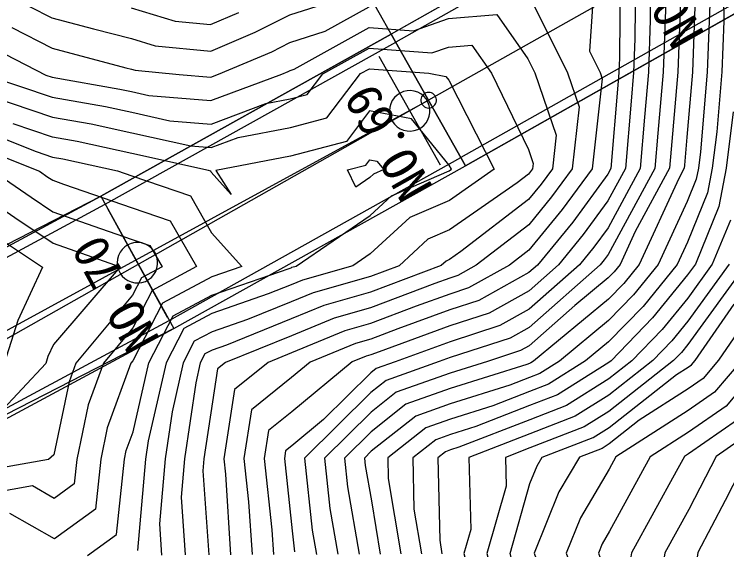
# Model space of a CAD drawing. Extents: x 42655 to 43811, y -141820 to -141156.
# Drawn here: x 42750.61 to 42796.32, y -141642.88 to -141608.54 of the extents above; entities that cross this region are included whole.
import ezdxf

# ---------------------------------------------------------------- set-up
doc = ezdxf.new("R2010")
doc.units = 0
for name, color, linetype in [('D-BMK-HTXT_1', 7, 'Continuous'), ('D-BMK_1', 7, 'Continuous'), ('D-STR-STR2トンネル', 7, 'Continuous'), ('ZE_HICN', 7, 'Continuous'), ('ZE_LWCN', 7, 'Continuous'), ('着色', 7, 'Continuous')]:
    doc.layers.add(name, color=color, linetype=linetype)

msp = doc.modelspace()

# ---------------------------------------------------------------- linework, layer by layer
at = {"layer": 'D-BMK-HTXT_1'}
for p, q in [((42777.191, -141614.053), (42738.344, -141545.264)), ((42777.945, -141618.22), (42774.016, -141611.252)), ((42777.191, -141614.053), (42724.628, -141643.736)), ((42760.439, -141627.975), (42756.58, -141620.967))]:
    msp.add_line(p, q, dxfattribs=at)
for points in [[(42774.68, -141614.736), (42774.701, -141614.968), (42774.763, -141615.193), (42774.864, -141615.403), (42775.001, -141615.591), (42775.17, -141615.752), (42775.364, -141615.881), (42775.579, -141615.972), (42775.806, -141616.024), (42776.039, -141616.035), (42776.27, -141616.003), (42776.491, -141615.931), (42776.696, -141615.821), (42776.879, -141615.676), (42777.032, -141615.5), (42777.152, -141615.3), (42777.233, -141615.082), (42777.275, -141614.853), (42777.275, -141614.619), (42777.233, -141614.39), (42777.152, -141614.172), (42777.032, -141613.972), (42776.879, -141613.796), (42776.696, -141613.651), (42776.491, -141613.541), (42776.27, -141613.469), (42776.039, -141613.437), (42775.806, -141613.448), (42775.579, -141613.5), (42775.364, -141613.591), (42775.17, -141613.72), (42775.001, -141613.881), (42774.864, -141614.069), (42774.763, -141614.279), (42774.701, -141614.504), (42774.68, -141614.736)], [(42757.21, -141624.471), (42757.231, -141624.703), (42757.293, -141624.928), (42757.394, -141625.138), (42757.531, -141625.327), (42757.699, -141625.488), (42757.894, -141625.616), (42758.108, -141625.708), (42758.335, -141625.759), (42758.568, -141625.77), (42758.799, -141625.739), (42759.021, -141625.667), (42759.226, -141625.556), (42759.408, -141625.411), (42759.561, -141625.235), (42759.681, -141625.035), (42759.763, -141624.817), (42759.804, -141624.588), (42759.804, -141624.355), (42759.763, -141624.125), (42759.681, -141623.907), (42759.561, -141623.707), (42759.408, -141623.532), (42759.226, -141623.386), (42759.021, -141623.276), (42758.799, -141623.204), (42758.568, -141623.173), (42758.335, -141623.183), (42758.108, -141623.235), (42757.894, -141623.326), (42757.699, -141623.455), (42757.531, -141623.616), (42757.394, -141623.804), (42757.293, -141624.014), (42757.231, -141624.239), (42757.21, -141624.471)]]:
    msp.add_lwpolyline(points, dxfattribs=at)
at = {"layer": 'D-BMK_1'}
msp.add_line((42932.715, -141526.226), (42777.191, -141614.053), dxfattribs=at)
for points in [[(42777.191, -141613.553), (42777.099, -141613.561), (42777.01, -141613.587), (42776.928, -141613.628), (42776.854, -141613.683), (42776.792, -141613.752), (42776.743, -141613.83), (42776.71, -141613.916), (42776.693, -141614.007), (42776.693, -141614.099), (42776.71, -141614.19), (42776.743, -141614.276), (42776.792, -141614.354), (42776.854, -141614.422), (42776.928, -141614.478), (42777.01, -141614.519), (42777.099, -141614.544), (42777.191, -141614.553)], [(42777.191, -141614.553), (42777.283, -141614.544), (42777.371, -141614.519), (42777.454, -141614.478), (42777.528, -141614.422), (42777.59, -141614.354), (42777.638, -141614.276), (42777.672, -141614.19), (42777.689, -141614.099), (42777.689, -141614.007), (42777.672, -141613.916), (42777.638, -141613.83), (42777.59, -141613.752), (42777.528, -141613.683), (42777.454, -141613.628), (42777.371, -141613.587), (42777.283, -141613.561), (42777.191, -141613.553)], [(42724.628, -141642.707), (42777.191, -141614.053)]]:
    msp.add_lwpolyline(points, dxfattribs=at)
at = {"layer": 'D-STR-STR2トンネル'}
for p, q in [((43087.053, -141433.469), (42774.793, -141609.807)), ((43087.348, -141433.992), (42775.088, -141610.33)), ((43091.527, -141441.393), (42779.268, -141617.731)), ((43091.822, -141441.915), (42779.563, -141618.253))]:
    msp.add_line(p, q, dxfattribs=at)
for points in [[(42756.158, -141620.2), (42774.793, -141609.807)], [(42756.447, -141620.726), (42775.088, -141610.33)], [(42760.547, -141628.171), (42779.268, -141617.731)], [(42760.837, -141628.697), (42779.563, -141618.253)], [(42724.628, -141637.196), (42756.158, -141620.2)], [(42724.628, -141637.875), (42756.447, -141620.726)], [(42724.628, -141647.478), (42760.547, -141628.171)], [(42724.628, -141648.156), (42760.837, -141628.697)]]:
    msp.add_lwpolyline(points, dxfattribs=at)
at = {"layer": 'ZE_HICN'}
for points in [[(42783.548, -141607.155), (42786.106, -141612.286), (42786.855, -141614.481), (42786.406, -141618.447), (42785.086, -141620.242), (42783.617, -141622.038), (42780.244, -141624.639), (42779.077, -141625.289), (42778.545, -141625.461), (42777.589, -141625.811), (42773.466, -141627.37), (42771.14, -141628.024), (42768.386, -141629.163), (42764.153, -141630.876), (42763.644, -141631.287), (42763.317, -141633.394), (42762.773, -141637.045), (42762.707, -141637.81), (42763.09, -141643.207)], [(42792.403, -141607.698), (42792.235, -141612.257), (42791.9, -141616.161), (42791.713, -141618.423), (42788.714, -141623.947), (42788.461, -141624.291), (42788.207, -141624.602), (42783.648, -141628.626), (42782.426, -141629.307), (42778.569, -141630.554), (42777.863, -141630.812), (42774.467, -141632.015), (42773.491, -141632.786), (42769.23, -141637.015), (42769.721, -141641.628), (42769.991, -141643.174)], [(42750.462, -141609.398), (42753.035, -141610.715), (42757.758, -141611.969), (42758.129, -141612.062), (42758.363, -141612.133), (42761.184, -141612.402), (42763.22, -141612.573), (42763.708, -141612.39), (42767.123, -141610.947), (42768.298, -141610.356), (42770.549, -141609.628), (42773.376, -141608.061)], [(42796.733, -141614.799), (42796.277, -141618.401), (42795.822, -141620.867), (42794.306, -141624.573), (42793.809, -141625.259), (42791.562, -141628.012), (42788.894, -141630.761), (42788.747, -141630.876), (42785.463, -141632.95), (42783.671, -141633.637), (42780.227, -141634.98), (42778.592, -141635.493), (42777.645, -141635.828), (42776.183, -141636.983), (42776.25, -141640.283), (42776.729, -141643.143)], [(42747.97, -141615.729), (42752.022, -141617.343), (42753.067, -141617.695), (42753.721, -141617.808), (42757.224, -141618.583), (42758.161, -141618.905), (42761.908, -141620.193), (42763.267, -141622.547), (42765.215, -141624.709), (42763.28, -141625.375), (42760.127, -141627.067), (42758.216, -141630.757), (42758.093, -141630.904), (42756.569, -141635.054), (42756.152, -141637.076), (42755.811, -141640.273), (42753.181, -141642.187), (42750.332, -141640.545)], [(42772.513, -141619.622), (42771.991, -141618.514), (42773.173, -141618.206), (42773.421, -141617.879), (42773.868, -141617.965), (42774.309, -141618.504), (42773.657, -141618.787), (42773.427, -141618.999), (42772.513, -141619.622)], [(42798.902, -141626.221), (42795.789, -141630.729), (42794.8, -141631.897), (42793.843, -141632.56), (42790.693, -141634.579), (42788.771, -141636.09), (42788.318, -141636.376), (42786.864, -141636.933), (42785.536, -141639.167), (42783.963, -141643.109), (42785.426, -141647.217), (42785.521, -141649.265), (42786.771, -141651.77), (42788.291, -141655.415), (42786.654, -141658.892), (42785.999, -141661.588), (42786.78, -141664.154), (42788.915, -141666.931), (42789.563, -141667.734), (42791.86, -141670.338), (42794.029, -141672.519)], [(42797.674, -141636.883), (42796.215, -141639.722), (42794.464, -141643.06), (42793.909, -141646.814), (42793.595, -141648.835), (42793.615, -141649.227), (42793.926, -141650.324), (42795.097, -141655.383), (42793.966, -141658.916), (42792.98, -141661.555), (42793.984, -141662.795), (42797.426, -141665.688)]]:
    msp.add_lwpolyline(points, dxfattribs=at)
at = {"layer": 'ZE_LWCN'}
for points in [[(42787.84, -141606.115), (42787.511, -141610.896), (42788.199, -141612.276), (42788.335, -141612.672), (42787.681, -141618.441), (42785.761, -141621.052), (42783.625, -141623.664), (42782.373, -141624.629), (42779.747, -141626.093), (42778.55, -141626.48), (42776.398, -141627.267), (42773.47, -141628.374), (42771.819, -141628.838), (42768.391, -141630.256), (42766.889, -141630.864), (42764.738, -141632.599), (42764.048, -141637.039), (42764.155, -141638.027), (42764.49, -141643.2)], [(42789.475, -141606.108), (42789.432, -141611.33), (42789.398, -141612.271), (42789.329, -141613.076), (42788.887, -141618.436), (42788.691, -141618.797), (42786.436, -141621.862), (42784.18, -141624.62), (42783.632, -141625.104), (42780.416, -141626.896), (42778.554, -141627.499), (42775.208, -141628.722), (42773.475, -141629.377), (42772.498, -141629.652), (42769.599, -141630.851), (42768.398, -141631.84), (42765.831, -141633.91), (42765.346, -141637.033), (42765.646, -141639.817), (42765.866, -141643.194)], [(42790.455, -141606.103), (42790.423, -141610.119), (42790.344, -141612.266), (42790.186, -141614.104), (42789.829, -141618.431), (42788.699, -141620.514), (42787.111, -141622.672), (42785.522, -141624.614), (42783.637, -141626.278), (42781.086, -141627.7), (42778.559, -141628.517), (42774.017, -141630.178), (42773.48, -141630.381), (42773.176, -141630.466), (42772.277, -141630.838), (42768.408, -141634.025), (42766.924, -141635.222), (42766.644, -141637.027), (42767.138, -141641.607), (42767.241, -141643.187)], [(42791.435, -141606.099), (42791.413, -141608.909), (42791.289, -141612.262), (42791.043, -141615.133), (42790.771, -141618.427), (42788.706, -141622.23), (42787.786, -141623.482), (42786.865, -141624.608), (42783.643, -141627.452), (42781.756, -141628.503), (42778.564, -141629.536), (42775.036, -141630.826), (42773.831, -141631.252), (42773.485, -141631.526), (42770.457, -141634.531), (42768.418, -141636.21), (42768.018, -141636.534), (42767.942, -141637.021), (42768.444, -141641.672), (42768.587, -141643.015)], [(42796.082, -141606.077), (42796.129, -141608.979), (42796.01, -141612.24), (42795.681, -141616.085), (42795.387, -141618.405), (42795.094, -141619.993), (42793.799, -141623.159), (42793.145, -141624.579), (42790.947, -141627.273), (42788.741, -141629.546), (42787.261, -141630.769), (42784.892, -141632.265), (42783.667, -141632.734), (42781.313, -141633.653), (42778.587, -141634.507), (42777.009, -141635.065), (42774.573, -141636.99), (42774.6, -141638.302), (42775.411, -141643.149)], [(42793.393, -141606.487), (42793.181, -141612.253), (42792.757, -141617.189), (42792.656, -141618.418), (42790.451, -141622.48), (42789.476, -141624.596), (42789.099, -141625.057), (42788.721, -141625.446), (42786.569, -141627.226), (42783.653, -141629.799), (42783.095, -141630.11), (42780.97, -141630.798), (42778.573, -141631.549), (42775.103, -141632.777), (42773.497, -141634.046), (42770.511, -141637.009), (42770.856, -141640.241), (42771.366, -141643.168)], [(42794.324, -141606.813), (42794.125, -141612.249), (42793.768, -141616.428), (42793.614, -141618.218), (42793.598, -141618.414), (42793.246, -141619.062), (42790.699, -141624.59), (42789.715, -141625.796), (42788.728, -141626.813), (42783.925, -141630.784), (42783.749, -141630.895), (42783.659, -141630.93), (42783.484, -141630.998), (42778.578, -141632.535), (42775.738, -141633.54), (42773.503, -141635.307), (42771.793, -141637.003), (42771.99, -141638.854), (42772.741, -141643.162)], [(42751.577, -141608.035), (42753.026, -141608.777), (42755.687, -141609.484), (42758.12, -141610.093), (42759.65, -141610.559), (42763.212, -141610.899), (42766.074, -141609.689), (42768.29, -141608.575), (42772.534, -141607.202)], [(42758.111, -141608.124), (42760.938, -141608.985), (42763.204, -141609.201), (42765.026, -141608.431)], [(42795.227, -141607.896), (42795.067, -141612.244), (42794.629, -141617.371), (42794.498, -141618.41), (42794.367, -141619.12), (42793.787, -141620.537), (42791.922, -141624.584), (42790.331, -141626.535), (42788.734, -141628.179), (42785.593, -141630.776), (42784.321, -141631.58), (42783.663, -141631.832), (42782.399, -141632.325), (42778.582, -141633.521), (42776.374, -141634.303), (42773.508, -141636.567), (42773.075, -141636.997), (42773.125, -141637.467), (42773.523, -141639.752), (42774.093, -141643.155)], [(42749.348, -141610.76), (42752.631, -141612.442), (42753.044, -141612.581), (42757.381, -141613.334), (42758.136, -141613.501), (42759.238, -141613.744), (42763.227, -141614.08), (42767.778, -141612.371), (42768.171, -141612.205), (42768.306, -141612.137), (42768.565, -141612.054), (42773.382, -141609.383), (42776.22, -141609.606), (42778.467, -141608.821), (42781.558, -141608.563), (42783.568, -141611.405), (42784.012, -141612.296), (42785.376, -141616.29), (42785.131, -141618.453), (42784.411, -141619.432), (42783.61, -141620.412), (42779.264, -141623.763), (42778.539, -141624.267), (42778.309, -141624.368), (42778.003, -141624.649), (42773.461, -141626.366), (42770.462, -141627.21), (42768.381, -141628.07), (42764.229, -141629.751), (42763.302, -141630.07), (42762.838, -141630.319), (42762.545, -141630.884), (42762.254, -141632.166), (42761.526, -141637.051), (42761.313, -141639.514), (42761.576, -141643.214)], [(42748.89, -141612.459), (42753.05, -141613.859), (42756.466, -141614.452), (42758.142, -141614.823), (42760.588, -141615.364), (42763.234, -141615.587), (42766.758, -141614.264), (42768.315, -141613.965), (42769.401, -141613.681), (42770.405, -141612.359), (42773.388, -141610.705), (42777.399, -141611.02), (42778.476, -141610.644), (42779.957, -141610.52), (42781.221, -141612.309), (42783.595, -141617.215), (42783.897, -141618.099), (42783.856, -141618.459), (42783.736, -141618.622), (42783.602, -141618.786), (42782.878, -141619.344), (42778.531, -141622.371), (42777.146, -141622.972), (42775.311, -141624.662), (42773.456, -141625.363), (42769.783, -141626.396), (42768.375, -141626.978), (42765.567, -141628.114), (42763.296, -141628.896), (42762.16, -141629.506), (42761.444, -141630.889), (42760.73, -141634.029), (42760.279, -141637.057), (42759.919, -141641.218), (42760.061, -141643.221)], [(42749.064, -141613.794), (42753.055, -141615.138), (42755.551, -141615.571), (42758.148, -141616.146), (42761.938, -141616.984), (42763.241, -141617.094), (42764.976, -141616.442), (42768.323, -141615.799), (42770.658, -141615.189), (42772.817, -141612.348), (42773.394, -141612.028), (42777.212, -141612.327), (42778.306, -141612.539), (42778.486, -141612.758), (42781.4, -141618.471), (42778.522, -141620.475), (42775.983, -141621.577), (42773.449, -141623.909), (42772.326, -141624.676), (42769.105, -141625.581), (42768.37, -141625.885), (42766.906, -141626.478), (42763.291, -141627.723), (42761.482, -141628.693), (42760.343, -141630.894), (42759.206, -141635.893), (42759.032, -141637.063), (42758.525, -141642.922)], [(42755.315, -141643.243), (42757.165, -141641.897), (42757.68, -141637.069), (42757.793, -141636.523), (42758.238, -141635.312), (42759.241, -141630.899), (42760.804, -141627.88), (42763.285, -141626.549), (42768.244, -141624.841), (42768.365, -141624.792), (42768.426, -141624.767), (42768.692, -141624.692), (42773.438, -141621.454), (42774.82, -141620.182), (42778.513, -141618.579), (42778.65, -141618.483), (42778.511, -141618.211), (42776.087, -141615.252), (42773.407, -141614.735), (42771.916, -141616.698), (42768.332, -141617.633), (42763.541, -141618.554), (42764.527, -141620.09), (42763.248, -141618.671), (42763.209, -141618.603), (42763.072, -141618.556), (42758.155, -141617.468), (42754.636, -141616.69), (42753.061, -141616.416), (42750.543, -141615.569)], [(42747.975, -141616.916), (42752.219, -141618.606), (42752.763, -141618.979), (42753.074, -141619.187), (42753.762, -141619.431), (42758.171, -141620.946), (42760.608, -141621.783), (42762.303, -141624.722), (42759.449, -141626.254), (42758.207, -141628.653), (42756.327, -141630.913), (42755.345, -141633.586), (42754.625, -141637.083), (42754.457, -141638.649), (42753.169, -141639.586), (42751.774, -141638.782), (42748.08, -141639.434)], [(42749.278, -141618.62), (42751.7, -141620.279), (42753.084, -141621.2), (42756.142, -141622.286), (42758.18, -141622.986), (42759.307, -141623.374), (42760.091, -141624.732), (42758.771, -141625.441), (42758.197, -141626.55), (42754.56, -141630.921), (42754.121, -141632.117), (42753.156, -141636.8), (42752.807, -141637.092), (42748.073, -141637.927)], [(42747.989, -141619.765), (42750.638, -141621.579), (42753.093, -141623.214), (42757.406, -141624.745), (42753.123, -141629.708), (42752.763, -141630.489), (42752.623, -141630.93), (42748.063, -141635.813)], [(42796.55, -141621.74), (42795.393, -141624.568), (42793.816, -141626.744), (42792.178, -141628.751), (42790.233, -141630.755), (42788.752, -141631.919), (42786.034, -141633.636), (42783.676, -141634.539), (42779.141, -141636.308), (42778.596, -141636.479), (42778.281, -141636.59), (42777.793, -141636.975), (42777.901, -141642.263), (42778.047, -141643.137)], [(42749.575, -141622.878), (42752.412, -141624.768), (42750.84, -141628.181), (42749.959, -141630.942)], [(42796.48, -141624.563), (42793.823, -141628.228), (42792.794, -141629.49), (42791.572, -141630.749), (42788.756, -141632.962), (42786.605, -141634.321), (42783.68, -141635.441), (42779.771, -141636.966), (42779.898, -141641.581), (42779.456, -141643.13), (42779.826, -141644.573), (42781.2, -141649.285), (42783.77, -141654.912), (42783.934, -141655.239), (42784.015, -141655.434), (42783.927, -141655.621), (42783.777, -141656.241), (42782.665, -141661.603), (42783.822, -141666.034), (42784.208, -141667.299), (42784.56, -141667.757), (42788.943, -141672.982)], [(42797.567, -141624.558), (42793.83, -141629.713), (42793.41, -141630.228), (42792.911, -141630.742), (42788.761, -141634.005), (42787.176, -141635.006), (42783.684, -141636.343), (42782.116, -141636.955), (42782.167, -141638.807), (42780.935, -141643.123), (42781.967, -141647.141), (42782.59, -141649.278), (42783.756, -141651.83), (42784.879, -141654.083), (42785.44, -141655.428), (42784.836, -141656.711), (42783.799, -141660.982), (42783.671, -141661.599), (42783.804, -141662.108), (42785.065, -141666.251), (42786.217, -141667.75), (42788.934, -141670.988)], [(42791.018, -141671.367), (42788.924, -141668.993), (42787.874, -141667.742), (42785.923, -141665.202), (42784.824, -141661.593), (42785.745, -141657.802), (42786.866, -141655.421), (42785.825, -141652.926), (42784.002, -141649.272), (42783.989, -141648.974), (42783.74, -141648.275), (42782.414, -141643.117), (42783.695, -141638.629), (42784.146, -141637.498), (42784.475, -141636.944), (42787.747, -141635.691), (42788.766, -141635.047), (42793.091, -141631.647), (42793.836, -141631.169), (42794.063, -141631.012), (42794.297, -141630.736), (42796.794, -141627.12)], [(42797.281, -141630.722), (42795.538, -141632.781), (42793.849, -141633.951), (42789.214, -141636.922), (42788.779, -141637.719), (42786.927, -141640.835), (42786.023, -141643.1), (42786.863, -141645.459), (42787.04, -141649.258), (42787.716, -141650.614), (42788.851, -141653.335), (42789.671, -141655.408), (42788.869, -141657.207), (42787.563, -141659.982), (42787.174, -141661.582), (42787.638, -141663.105), (42788.905, -141664.754), (42791.306, -141667.726), (42792.702, -141669.309), (42794.02, -141670.634)], [(42798.773, -141630.715), (42796.275, -141633.666), (42793.856, -141635.343), (42791.407, -141636.912), (42788.797, -141641.695), (42788.317, -141642.503), (42788.083, -141643.09), (42788.301, -141643.702), (42788.559, -141649.251), (42788.662, -141649.457), (42788.835, -141649.873), (42791.021, -141655.402), (42788.883, -141660.198), (42788.472, -141661.073), (42788.349, -141661.577), (42788.495, -141662.057), (42788.894, -141662.576), (42793.048, -141667.718), (42793.544, -141668.279), (42794.012, -141668.75), (42795.553, -141669.568), (42799.114, -141671.881)], [(42797.012, -141634.55), (42793.862, -141636.734), (42793.6, -141636.902), (42793.075, -141637.865), (42790.199, -141643.08), (42789.979, -141644.497), (42790.223, -141649.243), (42790.941, -141651.779), (42792.37, -141655.396), (42790.488, -141659.621), (42789.759, -141661.57), (42794.002, -141666.81), (42795.072, -141667.708), (42799.107, -141670.328)], [(42797.75, -141635.435), (42795.647, -141636.892), (42794.964, -141638.221), (42793.879, -141640.29), (42792.346, -141643.07), (42791.787, -141646.666), (42791.919, -141649.235), (42793.512, -141654.864), (42793.72, -141655.389), (42793.446, -141656.003), (42791.369, -141661.563), (42793.993, -141664.803), (42797.438, -141667.697)]]:
    msp.add_lwpolyline(points, dxfattribs=at)
at = {"layer": '着色'}
msp.add_line((42760.837, -141628.697), (42760.837, -141628.697), dxfattribs=at)
msp.add_line((42760.837, -141628.697), (42760.837, -141628.697), dxfattribs=at)
msp.add_lwpolyline([(42779.563, -141618.253), (43091.823, -141441.915), (43087.053, -141433.469), (42774.793, -141609.807)], close=True, dxfattribs=at)
for points in [[(42774.793, -141609.807), (42756.158, -141620.2)], [(42779.563, -141618.253), (42779.563, -141618.253), (42774.793, -141609.807), (42774.793, -141609.807)], [(42760.837, -141628.697), (42779.563, -141618.253)], [(42654.785, -141672.308), (42756.158, -141620.2)], [(42756.158, -141620.2), (42756.158, -141620.2), (42760.837, -141628.697)], [(42756.158, -141620.2), (42756.158, -141620.2), (42760.837, -141628.697)], [(42760.837, -141628.697), (42654.786, -141683.055)]]:
    msp.add_lwpolyline(points, dxfattribs=at)

# ---------------------------------------------------------------- texts
at = {"layer": 'D-BMK-HTXT_1'}
for s, rotation, p in [('NO.68', 119.4534, (42794.918, -141609.784)), ('NO.69', 119.4135, (42777.499, -141619.619)), ('NO.70', 118.8406, (42759.98, -141629.37))]:
    msp.add_text(s, height=2.3065, rotation=rotation, dxfattribs=at).set_placement(p)

doc.saveas('drawing.dxf')
